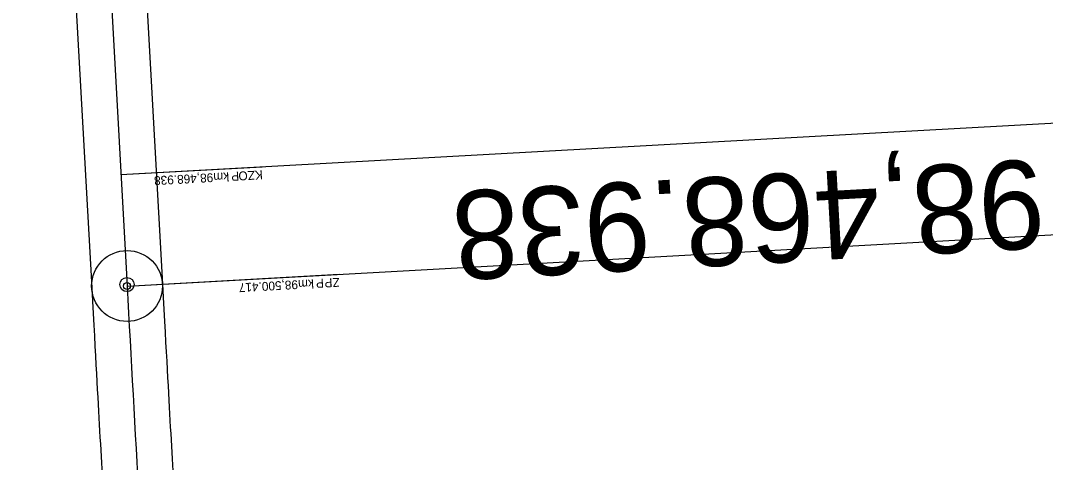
# Model space of a CAD drawing. Extents: x -678487 to -674601, y -1104811 to -1093295.
# Drawn here: x -677495 to -677205.5, y -1095345.6 to -1095220.8 of the extents above; entities that cross this region are included whole.
import ezdxf

# ---------------------------------------------------------------- set-up
doc = ezdxf.new("R2010")
doc.units = 0
for name, color, linetype in [('00_TUNEL', 7, 'Continuous'), ('SOxxxxxx_Koleje_hlavní_body_Popis', 7, 'Continuous'), ('SOxxxxxx_Koleje_hlavní_body_Popis10', 7, 'Continuous'), ('SOxxxxxx_Koleje_LN_staničení_zaoblení_Popis', 7, 'Continuous'), ('SOxxxxxx_Koleje_LN_staničení_zaoblení_Popis10', 7, 'Continuous'), ('SOxxxxxx_Osa_bod_P', 7, 'Continuous'), ('SOxxxxxx_Staničení_Popis', 7, 'Continuous')]:
    doc.layers.add(name, color=color, linetype=linetype)

msp = doc.modelspace()

# ---------------------------------------------------------------- linework, layer by layer
at = {"layer": '00_TUNEL'}
for p, q in [((-677474.01, -1094950.57), (-677454.95, -1095295.22)), ((-677493.99, -1094951.5), (-677474.92, -1095296.33))]:
    msp.add_line(p, q, dxfattribs=at)
for points in [[(-677454.95, -1095295.22), (-677453.82, -1095315.61), (-677452.69, -1095336), (-677451.12, -1095364.06), (-677450.68, -1095371.74), (-677450.24, -1095379.43)], [(-677474.92, -1095296.33), (-677473.79, -1095316.71), (-677472.66, -1095337.11), (-677471.09, -1095365.12), (-677470.66, -1095372.74), (-677470.22, -1095380.36)]]:
    msp.add_open_spline(points, degree=3, dxfattribs=at)
at = {"layer": 'SOxxxxxx_Koleje_hlavní_body_Popis'}
for q in [(-677405.02, -1095292.46), (-677464.93, -1095295.77)]:
    msp.add_line((-677464.93, -1095295.77), q, dxfattribs=at)
msp.add_circle((-677464.93, -1095295.77), 1, dxfattribs=at)
at = {"layer": 'SOxxxxxx_Koleje_hlavní_body_Popis10'}
for q in [(-676865.85, -1095262.64), (-677464.93, -1095295.77)]:
    msp.add_line((-677464.93, -1095295.77), q, dxfattribs=at)
msp.add_circle((-677464.93, -1095295.77), 10, dxfattribs=at)
at = {"layer": 'SOxxxxxx_Koleje_LN_staničení_zaoblení_Popis'}
msp.add_line((-677466.67, -1095264.34), (-677426.73, -1095262.13), dxfattribs=at)
at = {"layer": 'SOxxxxxx_Koleje_LN_staničení_zaoblení_Popis10'}
msp.add_line((-677466.67, -1095264.34), (-677067.28, -1095242.25), dxfattribs=at)
at = {"layer": 'SOxxxxxx_Osa_bod_P'}
msp.add_line((-677495.03, -1094751.61), (-677464.93, -1095295.77), dxfattribs=at)
msp.add_open_spline([(-677464.93, -1095295.77), (-677463.8, -1095316.16), (-677461.55, -1095356.94), (-677458.05, -1095418.1), (-677454.35, -1095479.24), (-677451.65, -1095519.99), (-677450.22, -1095540.36)], degree=3, dxfattribs=at)
at = {"layer": 'SOxxxxxx_Staničení_Popis'}
msp.add_line((-677464.95, -1095295.36), (-677464.95, -1095295.36), dxfattribs=at)
msp.add_circle((-677464.95, -1095295.36), 2, dxfattribs=at)

# ---------------------------------------------------------------- texts
at = {"layer": 'SOxxxxxx_Koleje_hlavní_body_Popis'}
for s, p in [('98,500.417', (-677416.73, -1095294.11)), (' km ', (-677411.32, -1095293.81)), ('P', (-677409.42, -1095293.71)), ('ZP', (-677404.97, -1095293.46))]:
    msp.add_text(s, height=2.5, rotation=183.1656, dxfattribs=at).set_placement(p)
at = {"layer": 'SOxxxxxx_Koleje_LN_staničení_zaoblení_Popis'}
for s, p in [('98,468.938', (-677440.66, -1095263.91)), (' km ', (-677435.25, -1095263.61)), ('P', (-677433.35, -1095263.5)), ('KZO', (-677426.68, -1095263.13))]:
    msp.add_text(s, height=2.5, rotation=183.1656, dxfattribs=at).set_placement(p)
at = {"layer": 'SOxxxxxx_Koleje_LN_staničení_zaoblení_Popis10'}
msp.add_text('98,468.938', height=25, rotation=183.1656, dxfattribs=at).set_placement((-677206.57, -1095259.97))

doc.saveas('drawing.dxf')
